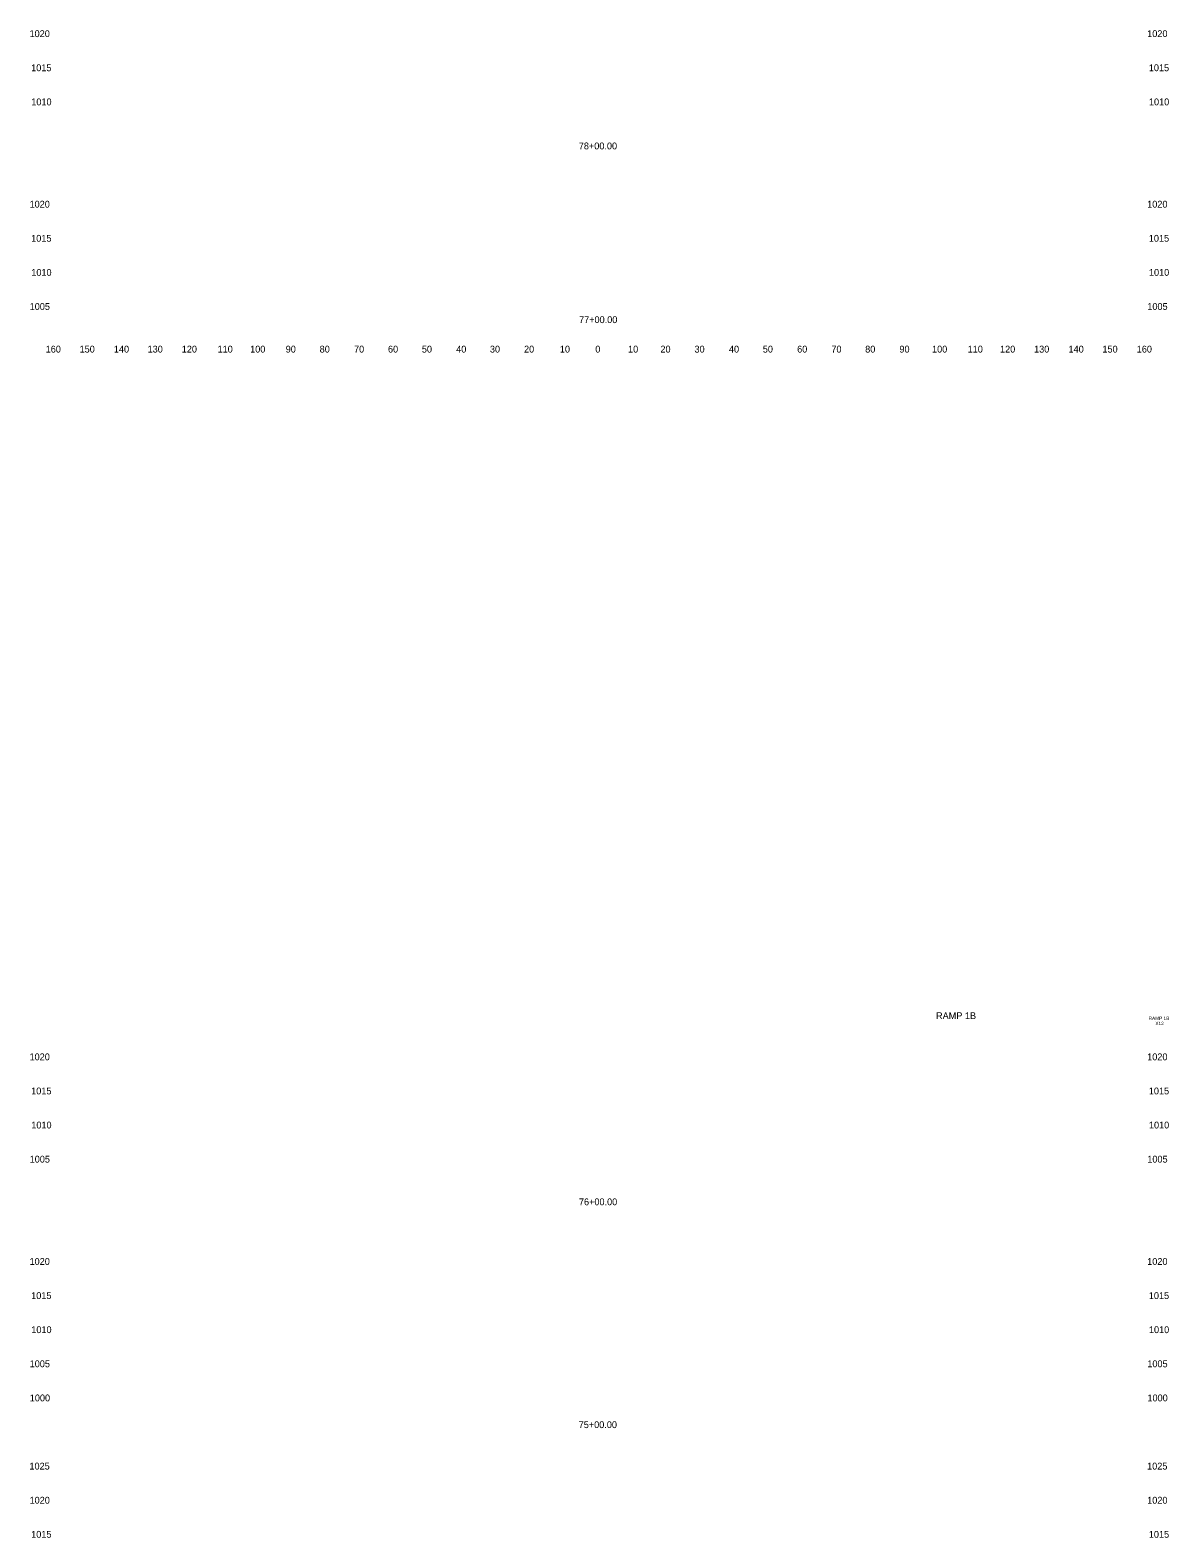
# Model space of a CAD drawing. Extents: x 4994 to 5843, y 4997 to 8804.
# Drawn here: x 5508.5 to 5842.5, y 5450 to 5892 of the extents above; entities that cross this region are included whole.
import ezdxf

# ---------------------------------------------------------------- set-up
doc = ezdxf.new("R2010")
doc.units = 0
for name, color, linetype in [('CLS_Search_Dist', 7, 'Continuous'), ('RD_XE_Ground', 7, 'Continuous'), ('UC_PD_Text', 7, 'Continuous')]:
    doc.layers.add(name, color=color, linetype=linetype)

msp = doc.modelspace()

# ---------------------------------------------------------------- texts
at = {"layer": 'CLS_Search_Dist'}
for s, p in [('1020', (5508.37, 5890)), ('1020', (5836.17, 5890)), ('1015', (5508.85, 5880)), ('1015', (5836.65, 5880)), ('1010', (5508.88, 5870)), ('1010', (5836.68, 5870)), ('1020', (5508.37, 5840)), ('1020', (5836.17, 5840)), ('1015', (5508.85, 5830)), ('1015', (5836.65, 5830)), ('1010', (5508.88, 5820)), ('1010', (5836.68, 5820)), ('1005', (5508.4, 5810)), ('1005', (5836.2, 5810)), ('160', (5513.1, 5797.5)), ('150', (5523.04, 5797.5)), ('140', (5533.1, 5797.5)), ('130', (5542.99, 5797.5)), ('120', (5553.01, 5797.5)), ('110', (5563.51, 5797.5)), ('100', (5573.07, 5797.5)), ('90', (5583.5, 5797.5)), ('80', (5593.46, 5797.5)), ('70', (5603.54, 5797.5)), ('60', (5613.5, 5797.5)), ('50', (5623.43, 5797.5)), ('40', (5633.5, 5797.5)), ('30', (5643.39, 5797.5)), ('20', (5653.4, 5797.5)), ('10', (5663.91, 5797.5)), ('0', (5674.3, 5797.5)), ('0', (5674.3, 5797.5)), ('10', (5683.91, 5797.5)), ('20', (5693.4, 5797.5)), ('30', (5703.39, 5797.5)), ('40', (5713.5, 5797.5)), ('50', (5723.43, 5797.5)), ('60', (5733.5, 5797.5)), ('70', (5743.54, 5797.5)), ('80', (5753.46, 5797.5)), ('90', (5763.5, 5797.5)), ('100', (5773.07, 5797.5)), ('110', (5783.51, 5797.5)), ('120', (5793.01, 5797.5)), ('130', (5802.99, 5797.5)), ('140', (5813.1, 5797.5)), ('150', (5823.04, 5797.5)), ('160', (5833.1, 5797.5)), ('1020', (5508.37, 5590)), ('1020', (5836.17, 5590)), ('1015', (5508.85, 5580)), ('1015', (5836.65, 5580)), ('1010', (5508.88, 5570)), ('1010', (5836.68, 5570)), ('1005', (5508.4, 5560)), ('1005', (5836.2, 5560)), ('1020', (5508.37, 5530)), ('1020', (5836.17, 5530)), ('1015', (5508.85, 5520)), ('1015', (5836.65, 5520)), ('1010', (5508.88, 5510)), ('1010', (5836.68, 5510)), ('1005', (5508.4, 5500)), ('1005', (5836.2, 5500)), ('1000', (5508.44, 5490)), ('1000', (5836.24, 5490)), ('1025', (5508.34, 5470)), ('1025', (5836.14, 5470)), ('1020', (5508.37, 5460)), ('1020', (5836.17, 5460)), ('1015', (5508.85, 5450)), ('1015', (5836.65, 5450))]:
    msp.add_text(s, height=2, dxfattribs=at).set_placement(p)
at = {"layer": 'RD_XE_Ground'}
for s, p in [('78+00.00', (5669.46, 5857.08)), ('77+00.00', (5669.54, 5806.14)), ('76+00.00', (5669.5, 5547.49)), ('75+00.00', (5669.43, 5482.15))]:
    msp.add_text(s, height=2, dxfattribs=at).set_placement(p)
at = {"layer": 'UC_PD_Text'}
for s, height, p in [('RAMP 1B', 2, (5774.24, 5602.06)), ('RAMP 1B', 1, (5836.59, 5601.8)), ('X12', 1, (5838.57, 5600.3))]:
    msp.add_text(s, height=height, dxfattribs=at).set_placement(p)

doc.saveas('drawing.dxf')
